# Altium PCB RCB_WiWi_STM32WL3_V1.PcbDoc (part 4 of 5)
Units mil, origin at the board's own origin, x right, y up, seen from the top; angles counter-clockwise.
Board outline 1250.1 x 2647.64 mil, 10 copper layers (L01-TOP, L02-GND, L03-SIG, L04-GND, L05-PWR, L06-PWR, L07-GND, L08-SIG, L09-GND, L10-BOT), stack 62.1 mil thick; 342 components, 203 nets, 969 pads, 708 vias.
Unrouted connection lines stored in the file: 108.
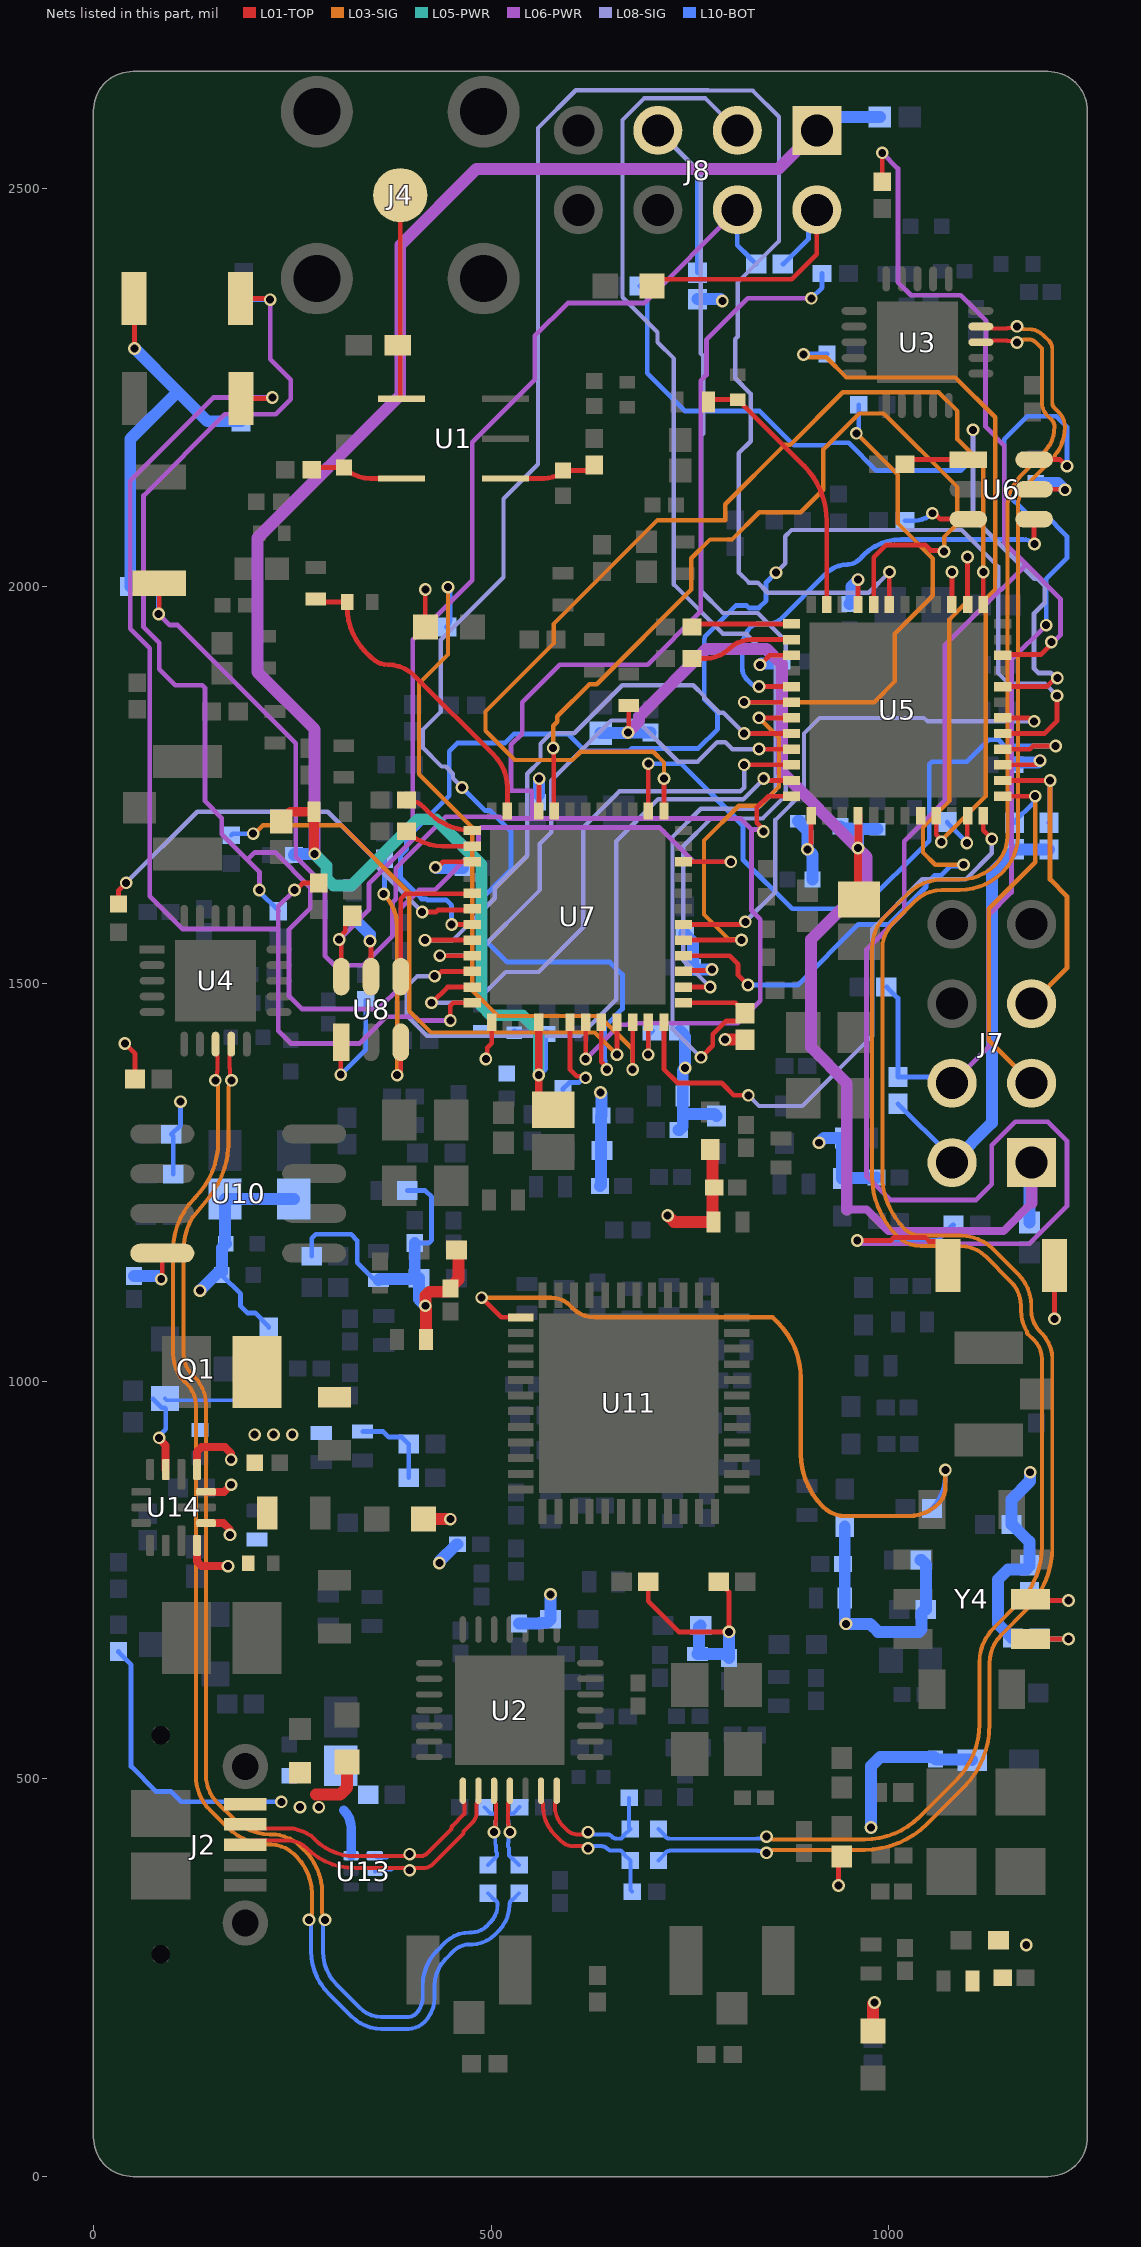
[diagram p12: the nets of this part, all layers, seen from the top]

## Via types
v1: diameter 16, hole 10, L01-TOP to L10-BOT, tented both sides, 699 vias
v2: diameter 16, hole 10, L01-TOP to L10-BOT, 9 vias

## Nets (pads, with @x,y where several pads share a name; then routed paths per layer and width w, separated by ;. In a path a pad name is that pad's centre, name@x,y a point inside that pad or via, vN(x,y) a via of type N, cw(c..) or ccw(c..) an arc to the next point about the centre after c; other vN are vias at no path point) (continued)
P3V3: C22.1 C23.1 C40.1 C41.1 C45.2 C54.2 C55.1 C71.1 C72.1 C76.1 C86.1 C90.1 C91.1 C96.1 C100.1 C101.1 C104.1 C106.1 C112.1 C113.1 C131.1 C132.1 C135.1 C137.1 C138.1 C139.1 C140.1 C141.2 C147.1 C148.1 C151.1 C153.1 C154.1 C155.1 C156.1 C157.2 D1.2 D2.2 D8.2 FB2.2 J7.2 J8.2 L2.1 L3.1 L6.1 L8.1 L10.2 L11.1 L13.1 L14.1 L16.1 L26.1 L29.1 R3.2 R18.1 R19.1 R20.2 R21.2 R22.1 R23.1 R28.2 R29.2 R31.2 R32.2 R49.2 R50.2 R52.1 R58.1 R69.1 R74.1 R78.1 R89.2 R90.2 R91.1 R95.2 R96.2 R101.1 R110.2 R111.2 R112.1 SW1.2 SW3.2 U5.3 U5.21 U5.27 U5.37 U6.5 U7.3 U7.21 U7.27 U7.37 U8.5 U10.8 | length 5166.3
  L01-TOP w6: v1(39.37,1425.2) 52.26,1412.31 R69.1@52.26,1380.51 ; SW3.2@51.18,2362.2 51.71,2361.68 v1(51.71,2299.21) ; v1(85.24,1128.61) 86.61,1129.98 U10.8@86.61,1161.42 ; v1(347.83,1553.87) 349.07,1552.63 U8.5@349.07,1509.25 ; v1(417.32,1996.06) 417.32,1949.18 D8.2@417.44,1949.06 ; v1(430.06,1646.7) 432.77,1646.7 439.61,1653.55 U7.27@476.38,1653.55 ; v1(493.43,1405.51) 495.34,1407.43 495.34,1419.88 500.97,1425.51 U7.37@500.98,1451.76 ; U7.21@560.04,1717.51 560.34,1717.81 560.34,1757.92 v1(560.64,1758.22) ; R32.2@697.83,748.03 697.83,723.43 736.22,685.04 v1(799.21,685.04) 799.21,735.24 796.21,738.24 796.21,739.22 787.4,748.03 R22.1@786.42,748.03 ; D2.2@702.76,2377.95 711.01,2386.2 878.33,2386.2 909.84,2417.72 J8.2@909.84,2473.62 ; U7.3@742.13,1515.72 743.39,1516.99 776.77,1516.99 v1(778.04,1518.26) ; v1(838.36,1901.35) 850.4,1913.4 U5.27@877.95,1913.4 ; v1(898.16,1669.29) 898.16,1672 902.56,1676.4 U5.37@902.56,1711.61 ; v1(937.01,366.14) 937.01,398.62 R3.2@940.94,402.56 ; U5.21@961.61,1977.35 961.66,1977.4 v1(961.71,2008.46) v1(961.71,2008.46) ; U5.3@1143.7,1775.57 1185.35,1775.57 v1(1190.6,1780.82) ; U6.5@1183.09,2122.05 1221.4,2122.05 v1(1221.99,2121.47) ; v1(1208.66,1078.74) SW1.2@1208.66,1145.67
  L01-TOP w15: C147.1@418.33,1052.98 418.33,1093.96 417.32,1094.97 v1(417.32,1095.24) 417.51,1095.43 417.51,1107.97 422.36,1112.82 446.24,1112.82 448.82,1115.4 448.82,1118.11 458.9,1128.19 458.9,1163.15 L29.1@456.69,1165.35 ; v1(722.13,1208.66) 722.41,1208.66 730.28,1200.79 C131.1@780.02,1200.79 778.66,1202.15 778.66,1288.87 L26.1@775.84,1291.69 ; v1(794.3,1430.11) 794.47,1429.93 819.41,1429.93 R111.2@819.58,1429.76 ; D1.2@980.31,183.07 980.31,216.88 v1(982.3,218.87)
  L10-BOT w6: R19.1@100.32,1260.63 100.32,1308.65 R18.1@98,1310.97 109.54,1322.52 v1(109.54,1351.94) ; R21.2@274.61,1157.48 274.61,1180.12 279.53,1185.04 323.97,1185.04 331.85,1177.17 331.85,1149.45 353.84,1127.46 C71.1@358.27,1127.46 ; C41.1@338.58,937.01 364.4,937.01 371.33,930.07 387.84,930.07 R50.2@396.65,921.26 396.58,921.18 R49.2@396.58,878.76 ; R20.2@394.69,1240.16 417.32,1240.16 425.2,1232.28 425.2,1177.54 421.68,1174.03 C96.1@404.08,1174.03 ; R112.1@867.13,2405.51 868.11,2405.51 899.16,2436.57 899.16,2462.94 J8.2@909.84,2473.62 ; R91.1@1011.81,1349.41 1075.61,1285.61 cw(c1065.19,1275.2) J7.2@1079.92,1275.2
  L10-BOT w15: R78.1@46.26,2000 46.26,2185.41 105.89,2245.03 ; C55.1@51.18,1132.5 81.09,1132.5 84.97,1128.61 v1(85.24,1128.61) ; v1(51.71,2299.21) 105.89,2245.03 ; R101.1@185.57,2207.68 143.24,2207.68 105.89,2245.03 ; C151.1@327.45,1582.68 347.64,1562.49 347.64,1554.06 v1(347.83,1553.87) ; C71.1@358.27,1127.46 359.5,1128.69 408.22,1128.69 L11.1@409.45,1129.92 ; C96.1@404.08,1174.03 404.08,1134.23 408.4,1129.92 L11.1@409.45,1129.92 ; v1(417.32,1095.24) 417.32,1095.51 409.45,1103.38 L11.1@409.45,1129.92 ; v1(430.06,1646.7) 430.33,1646.7 431.37,1645.67 C155.1@464.57,1645.67 ; v1(435.04,771.65) 435.23,771.84 435.23,773.81 456.69,795.28 R52.1@457.68,795.28 ; C76.1@535.43,695.49 560.23,695.49 561.21,696.48 570.49,696.48 L3.1@574.8,700.79 v1(574.8,732.28) ; C154.1@560.45,1737.61 560.45,1758.03 v1(560.64,1758.22) ; C86.1@637.16,1246 638.16,1246.99 638.16,1333.65 C72.1@639.15,1334.65 639.15,1362.18 v1(637.81,1363.52) ; C101.1@736.02,1316.46 737.37,1316.46 741.17,1320.25 741.17,1336.39 ; R74.1@736.9,1440.93 737.89,1440.93 742.2,1436.62 742.2,1435.64 744.25,1433.59 v1(744.25,1394.25) 741.17,1391.18 C100.1@741.17,1359.19 741.17,1336.39 ; R31.2@743.63,1563.96 743.63,1562.98 753.83,1552.78 C153.1@753.83,1521 756.56,1518.26 v1(778.04,1518.26) ; C104.1@759.84,656.99 C104.1@760.45,656.99 ; R110.2@759.84,2361.22 788.73,2361.22 v1(790.88,2359.07) ; L14.1@763.78,692.91 761.81,690.94 761.81,658.35 C104.1@760.45,656.99 ; L13.1@783.72,1333.74 781.07,1336.39 741.17,1336.39 ; C106.1@799.21,652.19 C106.1@799.21,653.54 ; v1(799.21,685.04) C106.1@799.21,653.54 ; v1(838.36,1901.35) 838.63,1901.35 840.05,1902.78 863.41,1902.78 C139.1@866.14,1905.51 ; C140.1@885.83,1704.72 887.8,1704.72 888.17,1704.35 888.17,1702.38 897.97,1692.58 897.97,1669.48 v1(898.16,1669.29) 898.16,1669.02 904.33,1662.85 C141.2@904.33,1631.21 ; v1(912.58,1300.22) 918.56,1306.2 C90.1@941.3,1306.2 941.49,1306 941.49,1255.61 L8.1@941.69,1255.42 942.18,1255.91 984.48,1255.91 C91.1@984.98,1256.41 ; C112.1@944.93,727.66 944.93,696.74 v1(946.57,695.09) 946.76,694.9 977.04,694.9 986.88,685.05 1038.18,685.05 1041.67,688.54 1041.67,708.88 1045.98,713.19 R29.2@1046.97,713.19 1046.97,769.96 1041.34,775.59 R28.2@1040.35,775.59 ; C112.1@944.93,727.66 L16.1@944.88,817.42 ; C138.1@950.77,1977.86 953.5,1980.6 953.5,1999.98 961.71,2008.19 v1(961.71,2008.46) ; v1(978.05,439.06) 977.96,439.15 977.96,516.08 989.56,527.67 1057.25,527.67 1059.06,525.87 C54.2@1059.06,524.93 1059.71,524.27 1104.66,524.27 FB2.2@1105.31,523.62 ; J7.2@1079.92,1275.2 1129.92,1325.2 1129.92,1639.96 1158.27,1668.31 R90.2@1158.27,1669.3 1158.4,1669.17 1201.57,1669.17 R89.2@1201.7,1669.04 ; R95.2@1156.5,677.17 1155.51,677.17 1137.8,694.88 1137.8,751.06 1150.15,763.41 1172.85,763.41 1177.17,767.72 R96.2@1177.17,768.7 1177.17,798.57 1155.71,820.02 R23.1@1154.72,820.02 1154.72,851.58 1177.92,874.77 1177.92,885.64 v1(1178.11,885.83) ; C137.1@1159.45,1775.57 1162.18,1778.3 1187.81,1778.3 1190.33,1780.82 v1(1190.6,1780.82) ; C135.1@1185.04,2129.92 1213.26,2129.92 1221.71,2121.47 v1(1221.99,2121.47) ; C104.1@760.45,656.99 794.41,656.99 795.27,656.12 796.63,656.12 C106.1@799.21,653.54
  other v1: 1173.23,291.34 202.76,933.07 226.38,933.07 250,933.07
P3V3_PGOOD: Q1.1 R53.1 U14.13 | length 277.9
  L01-TOP w10: v1(82.68,929.13) 82.68,927.51 90.87,919.32 U14.13@90.87,889.27
  L10-BOT w5: Q1.1@89.8,978.35 91.77,976.38 192.91,976.38 220.47,1003.94 R53.1@220.47,1034.45
  L10-BOT w6: Q1.1@74.8,978.35 86.17,966.98 89.49,966.98 90.87,965.6 90.87,940.03 82.68,931.84 v1(82.68,929.13)
RX_BOOTSEL: R59.2 R75.1 SW1.1 U5.10 | length 2692.8
  L01-TOP w6: v1(960.63,1177.17) 1002.71,1177.17 1006.64,1181.1 1046.01,1181.1 1050.98,1176.13 1062.06,1176.13 1074.8,1163.39 SW1.1@1074.8,1145.67 ; v1(992.07,2545.24) 992.13,2545.19 R59.2@992.13,2508.86 ; U5.10@1143.7,1913.4 1144.72,1914.42 1191.81,1914.42 1204.72,1927.33 v1(1204.72,1930.04)
  L06-PWR w6: v1(960.63,1177.17) 963.34,1177.17 967.27,1173.23 1177.17,1173.23 1224.41,1220.47 1224.41,1302.84 1200.48,1326.77 1159.36,1326.77 1129.92,1297.33 1129.92,1248.03 1110.24,1228.35 1001.98,1228.35 972.44,1257.89 972.44,1543.31 1019.68,1590.55 1019.68,1679.39 1070.87,1730.57 1070.87,1926.18 1140.74,1996.06 1141.73,1996.06 1171.76,2026.09 1171.76,2029.03 ; v1(992.07,2545.24) 1011.81,2525.5 1011.81,2382.57 1028.24,2366.14 1090.55,2366.14 1122.66,2334.03 1122.66,2312.01 1122.05,2311.39 1122.05,2200.79 1145.67,2177.17 1145.67,2055.12 1171.76,2029.03 ; v1(1204.72,1930.04) 1207.43,1930.04 1216.23,1938.84 1216.23,1984.56 1171.76,2029.03
  L10-BOT w6: v1(960.63,1177.17) 1061.02,1177.17 1080.71,1196.85 R75.1@1081.69,1196.85
RX_CLK: U5.29 U6.4 | length 558.1
  L01-TOP w6: v1(837.2,1874.11) 837.29,1874.01 U5.29@877.95,1874.02 ; U6.4@1183.09,2084.65 1183.09,2053.68 v1(1183.55,2053.22)
  L10-BOT w6: 822.12,1882.61 825.97,1878.76 ccw(c837.2,1889.99) 829.64,1876.02 ccw(c837.2,1889.99) v1(837.2,1874.11) ; 822.1,1882.62 cw(c837.1,1897.59) 815.91,1897.59 815.91,1922.6 cw(c852.99,1922.6) 826.77,1948.82 cw(c836.32,1939.27) 836.32,1952.78 848.14,1952.78 ccw(c848.14,1977.29) 865.47,1959.95 921.94,2016.42 cw(c948.82,1989.54) 948.82,2027.56 ccw(c948.82,2046.57) 962.26,2033.13 968.5,2039.37 cw(c1016.03,1991.85) 1016.03,2059.06 1169.46,2059.06 cw(c1169.46,2039.14) v1(1183.55,2053.22)
RX_CLK_SEL: J7.4 R91.2 R92.1 U6.6 | length 1295.9
  L01-TOP w6: U6.6@1183.09,2159.45 1215.81,2159.45 1224.08,2151.18 v1(1224.43,2151.18)
  L06-PWR w6: J7.4@1079.92,1375.2 1125.98,1421.26 1125.98,1586.61 1154.53,1615.16 1154.53,1907.48 v1(1198.3,1951.25)
  L10-BOT w6: R92.1@997.05,1496.06 998.03,1496.06 1011.81,1482.28 R91.2@1011.81,1382.87 1061.39,1382.87 cw(c1061.39,1356.66) J7.4@1079.92,1375.2 ; v1(1198.3,1951.25) 1198.3,2009.32 1224.41,2035.43 1224.41,2062.99 1196.85,2090.55 1174.8,2090.55 1145.67,2119.69 1145.67,2185.04 1174.68,2214.05 1211.15,2214.05 1224.43,2200.76 v1(1224.43,2151.18)
RX_DETECT: R73.1 U5.47 | length 71.5
  L01-TOP w6: v1(1098.43,1677.17) 1098.92,1677.66 1098.92,1711.11 U5.47@1099.41,1711.61
  L10-BOT w6: R73.1@1073.82,1703.65 1073.82,1702.67 1098.43,1678.06 v1(1098.43,1677.17)
RX_DPLL_48MHz: R87.2 U6.3 | length 85.3
  L01-TOP w6: v1(1055.12,2092.02) 1057.82,2092.02 1065.2,2084.65 U6.3@1100.37,2084.65
  L10-BOT w6: R87.2@1020.67,2082.68 1032.56,2082.68 ccw(c1032.56,2114.58) v1(1055.12,2092.02)
RX_FTDI_USB_N: C116.2 R13.1 U2.6 | length 210
  L01-TOP w5: U2.6@562.99,485.24 562.99,473.32 ccw(c566.99,473.32) 564.16,470.49 cw(c561.34,467.66) 565.33,467.66 565.33,465.55 ccw(c615.08,465.55) 579.91,430.38 588.23,422.05 ccw(c604.24,438.06) 604.24,415.42 619.4,415.42 cw(c619.4,412.77) v1(622.05,412.77)
  L10-BOT w5: v1(622.05,412.77) cw(c624.7,412.77) 624.7,415.42 638.99,415.42 cw(c638.99,405.86) 645.75,412.62 ccw(c652.5,419.38) 652.5,409.82 661.87,409.82 cw(c661.87,404.82) 665.4,408.36 666.87,406.89 ccw(c669.11,406.89) 667.52,405.31 R13.1@675.2,397.64 675.2,360.63 C116.2@677.56,358.27
RX_FTDI_USB_P: C53.2 R14.1 U2.7 | length 185.8
  L01-TOP w5: U2.7@582.68,485.24 582.68,473.32 cw(c578.68,473.32) 581.51,470.49 ccw(c584.33,467.66) 580.33,467.66 580.33,465.61 ccw(c615.22,465.61) 590.55,440.95 596.64,434.86 ccw(c607.35,445.56) 607.35,430.42 619.4,430.42 ccw(c619.4,433.07) v1(622.05,433.07)
  L10-BOT w5: v1(622.05,433.07) ccw(c624.7,433.07) 624.7,430.42 645.2,430.42 cw(c645.2,420.86) 651.96,427.62 ccw(c658.72,434.38) 658.72,424.82 661.87,424.82 ccw(c661.87,429.82) 665.4,426.28 666.87,427.75 cw(c669.11,427.75) 667.53,429.34 R14.1@675.2,437.01 673.62,438.58 C53.2@673.62,476.38
RX_LCL_48MHz: R83.2 U6.1 | length 82.2
  L01-TOP w6: R83.2@1020.67,2153.54 1026.57,2159.45 U6.1@1100.37,2159.45
RX_LED0: R72.1 U5.8 | length 1071.9
  L01-TOP w6: U5.8@1143.7,1874.02 1198.94,1874.02 1209.67,1884.74 v1(1212.26,1884.74)
  L08-SIG w6: v1(1106.3,2196.85) 1106.3,2086.61 1183.37,2009.54 1187.44,2009.54 1196.4,2000.58 1196.4,1979.45 1183,1966.04 1183,1896.64 1188.55,1891.08 1203.74,1891.08 1210.08,1884.74 v1(1212.26,1884.74)
  L10-BOT w6: R72.1@687.01,2377.95 687.69,2377.95 696.5,2369.14 696.5,2268.06 744.09,2220.47 838.05,2220.47 880.91,2177.61 923.66,2177.61 926.7,2180.65 949.81,2180.65 984.8,2145.67 1090.55,2145.67 1106.3,2161.42 v1(1106.3,2196.85)
RX_LED2: U5.15 | length 40.8
  L01-TOP w6: U5.15@1079.72,1977.35 1079.72,2018.02 v1(1079.82,2018.11)
RX_RF: C30.1 R9.2 U1.3 | length 117.2
  L01-TOP w6: U1.3@518.26,2135.79 566.69,2135.79 ccw(c566.69,2169.53) C30.1@590.55,2145.67 623.03,2145.67 R9.2@629.92,2152.56
RX_RF_RX: C20.1 L25.1 U5.23 | length 337.2
  L01-TOP w6: L25.1@773.66,2231.89 cw(c781.17,2224.38) 781.17,2235 C20.1@810.41,2235 892.95,2152.45 cw(c822.24,2081.74) 922.24,2081.74 U5.23@922.24,1977.35
RX_RF_TX: R5.1 U5.26 | length 131.3
  L01-TOP w6: R5.1@752.95,1909.45 770.7,1909.45 ccw(c770.7,1949.77) 799.21,1921.26 cw(c827.76,1892.71) 827.76,1933.09 U5.26@877.95,1933.09
RX_RF_TX_HP: R6.1 U5.25 | length 126.1
  L01-TOP w6: R6.1@752.95,1948.82 cw(c762.51,1939.26) 762.51,1952.78 U5.25@877.95,1952.78
RX_RST_N: R57.2 R78.2 SW2.1 U5.36 U7.43 | length 2870.6
  L01-TOP w6: v1(81.93,1965.25) 82.68,1966 SW2.1@82.68,2003.94 ; v1(619.09,1405.51) U7.43@619.09,1451.76 ; v1(842.58,1691.68) 842.58,1694.38 834.2,1702.76 834.2,1721.96 848.43,1736.19 U5.36@877.95,1736.19
  L06-PWR w6: v1(81.93,1965.25) 95.81,1951.37 105.7,1951.37 254.48,1802.59 254.48,1659.89 291.05,1623.32 291.05,1535.72 303.15,1523.62 339.22,1523.62 376.17,1560.57 376.17,1602.52 380.28,1606.63 380.28,1645.25 411.87,1676.84 411.87,1678.72 443.34,1710.19 510.85,1710.19 512.8,1708.23 551.18,1708.23 ; v1(619.09,1405.51) 662.15,1448.57 672.24,1448.57 674.11,1450.43 810.08,1450.43 838.58,1478.94 838.58,1581.12 827.79,1591.91 827.79,1694.09 ; v1(842.58,1691.68) 840.66,1693.59 836.18,1693.59 835.68,1694.09 827.79,1694.09 ; v1(902.9,2362.33) 822.96,2362.33 770.95,2310.32 770.95,2265.93 763.78,2258.75 763.78,1968.5 696.85,1901.57 586.61,1901.57 539.37,1854.33 539.37,1814.96 525.11,1800.7 525.11,1743.06 551.18,1743.06 551.18,1708.23 ; 551.18,1708.23 813.65,1708.23 827.79,1694.09
  L10-BOT w6: R78.2@79.72,2000 81.93,1997.8 v1(81.93,1965.25) ; v1(902.9,2362.33) 916.34,2375.77 R57.2@916.34,2393.7
RX_RX_SEQUENCE: R76.1 U7.42 | length 118.7
  L01-TOP w6: U7.42@599.41,1451.76 599.4,1392.25 607.84,1383.8 617.18,1383.8 v1(619.09,1381.89)
  L10-BOT w6: R76.1@590.55,1367.13 590.55,1368.11 598.38,1375.94 610.44,1375.94 616.39,1381.89 v1(619.09,1381.89)
RX_SPI1_MISO: U5.35 U7.34 | length 873.2
  L01-TOP w6: v1(429.13,1509.81) 431.84,1509.81 437.75,1515.72 U7.34@476.38,1515.72 ; v1(842.97,1758.32) 845.67,1758.32 848.11,1755.88 U5.35@877.95,1755.88
  L08-SIG w5.5: v1(429.13,1509.81) 407.45,1509.81 393.7,1496.06 393.7,1460.63 419.46,1434.87 612.03,1434.87 657.48,1480.32 657.48,1679.46 710.16,1732.15 817.48,1732.15 842.97,1757.64 v1(842.97,1758.32)
RX_SPI1_MOSI: U5.34 U7.35 | length 726.7
  L01-TOP w6: v1(425.04,1476.34) 425.66,1476.34 445.34,1496.02 U7.35@476.38,1496.03 ; v1(818.43,1775.56) U5.34@877.95,1775.57
  L08-SIG w5.5: v1(425.04,1476.34) 479.7,1476.34 518.41,1515.05 559.98,1515.05 616.08,1571.15 616.08,1696.85 661.46,1742.24 813.71,1742.24 818.43,1746.96 v1(818.43,1775.56)
RX_SPI1_NSS: U5.33 U7.33 | length 713.2
  L01-TOP w6: v1(435.62,1535.5) 435.72,1535.4 U7.33@476.38,1535.41 ; v1(837.2,1795.35) 837.29,1795.25 U5.33@877.95,1795.26
  L08-SIG w5.5: v1(435.62,1535.5) 478.78,1535.5 561.51,1618.22 561.51,1676.3 575.69,1690.48 575.69,1755.73 651.36,1831.4 683.56,1831.4 735.43,1779.53 759.84,1779.53 784.35,1804.03 794.79,1804.03 803.48,1795.35 v1(837.2,1795.35)
RX_SPI1_SCK: U5.32 U7.32 | length 759.4
  L01-TOP w6: v1(416.86,1555.09) U7.32@476.38,1555.1 ; v1(818.43,1814.94) U5.32@877.95,1814.95
  L08-SIG w5.5: v1(416.86,1555.09) 452.06,1555.09 504.63,1607.67 504.63,1620.41 545.59,1661.36 545.59,1764.45 562.29,1781.16 562.29,1802.1 575.46,1815.26 604.66,1815.26 664.92,1875.53 754.27,1875.53 768.41,1861.38 768.41,1859.91 787.23,1841.1 792.28,1841.1 v1(818.43,1814.94)
RX_SPI3_MISO: U5.5 U7.31 | length 1609.4
  L01-TOP w6: v1(450.47,1574.79) U7.31@476.38,1574.79 ; U5.5@1143.7,1814.95 1196.14,1814.95 1212.01,1830.82 v1(1212.01,1862.45)
  L08-SIG w5.5: v1(858.38,2017.26) 870.08,2028.96 870.08,2062.99 877.95,2070.87 1091.99,2070.87 1137.79,2025.06 1137.79,1891.02 1151.08,1877.74 1196.72,1877.74 v1(1212.01,1862.45)
  L10-BOT w6: v1(450.47,1574.79) 450.47,1599.01 443.82,1605.66 419.99,1605.66 418.69,1606.96 412.74,1606.96 386.27,1633.43 386.27,1661.87 393.7,1669.29 393.7,1683.05 447.34,1736.7 447.34,1792.52 457.97,1803.15 517.7,1803.15 529.06,1814.51 596.71,1814.51 618.13,1793.09 673.94,1793.09 677.03,1796.18 760.75,1796.18 784.92,1820.35 784.92,1841.06 768.16,1857.81 768.16,1933.52 768.73,1934.08 768.73,1936.56 808.05,1975.89 821.37,1975.89 824.37,1972.89 837.05,1972.89 846.01,1981.85 846.01,2004.89 v1(858.38,2017.26)
RX_SPI3_MOSI: U5.31 U7.5 | length 486.5
  L01-TOP w6: U7.5@742.13,1555.1 v1@814.95,1555.11 ; v1(837.2,1834.73) 837.29,1834.63 U5.31@877.95,1834.64
  L03-SIG w5.5: v1(814.96,1555.12) 813.64,1556.44 798.71,1556.44 767.83,1587.32 767.83,1680.41 811.57,1724.14 838.14,1724.14 862.2,1748.2 862.2,1809.72 v1(837.2,1834.73)
RX_SPI3_NSS: U5.6 U7.6 | length 687.1
  L01-TOP w6: U7.6@742.13,1574.79 813.84,1574.79 817.2,1578.15 v1(819.91,1578.15) ; U5.6@1143.7,1834.64 1176.05,1834.64 1180.43,1830.25 v1(1183.14,1830.25)
  L08-SIG w5.5: v1(819.91,1578.15) 857.72,1615.97 857.72,1706.34 893.7,1742.32 893.7,1814.95 913.3,1834.54 1044.65,1834.54 1048.94,1830.25 v1(1183.14,1830.25)
RX_SPI3_SCK: U5.13 U7.13 | length 1387.1
  L01-TOP w6: U7.13@717.52,1717.51 717.52,1758.17 v1(717.62,1758.26) ; U5.13@1119.09,1977.35 1119.09,2018.02 v1(1119.19,2018.11)
  L03-SIG w5.5: v1(717.62,1758.26) 717.62,1778.52 704.06,1792.08 612.86,1792.08 602.5,1781.72 529.92,1781.72 493.11,1818.52 493.11,1842.51 578.74,1928.14 578.74,1952.76 709.34,2083.36 794.58,2083.36 794.58,2103.26 869.28,2177.96 876.41,2177.96 942.54,2244.09 1062.99,2244.09 1086.61,2220.47 1086.61,2185.04 1119.19,2152.47 v1(1119.19,2018.11)
RX_SWCLK: J7.5 R89.1 U5.2 | length 421.4
  L01-TOP w6: U5.2@1143.7,1755.88 v1(1203.22,1755.88)
  L03-SIG w6: J7.5@1179.92,1475.2 1224.41,1519.68 1224.41,1610.24 1203.22,1631.43 v1(1203.22,1755.88)
  L10-BOT w6: R89.1@1201.7,1702.51 1203.22,1704.03 v1(1203.22,1755.88)
RX_SWDIO: J7.3 R90.1 U5.1 | length 492.4
  L01-TOP w6: U5.1@1143.7,1736.19 1184.36,1736.19 v1(1184.46,1736.09)
  L03-SIG w6: J7.3@1179.92,1375.2 1125.98,1429.13 1125.98,1594.49 1184.46,1652.96 v1(1184.46,1736.09)
  L10-BOT w6: R90.1@1158.27,1702.76 1158.27,1703.75 1182.55,1728.02 1182.55,1734.18 v1(1184.46,1736.09)
RX_TX_SEQUENCE: U5.19 U7.44 | length 2733
  L01-TOP w6: U7.44@638.78,1451.76 638.78,1401.84 645.67,1394.95 v1(645.67,1392.24) ; U5.19@1000.98,1977.35 1000.98,2018.02 v1(1001.08,2018.11)
  L08-SIG w5.5: v1(463.54,1747.01) 463.54,1747.44 452.27,1758.72 452.27,1764.27 443.01,1773.53 437.86,1773.53 414.37,1797.01 414.37,1819.88 437.01,1842.52 437.01,1932.77 515.75,2011.51 515.75,2110.24 559.06,2153.54 559.06,2576.51 606.52,2623.97 773.35,2623.97 773.62,2623.71 829.05,2623.71 862.2,2590.55 862.2,2434.31 810.12,2382.22 810.12,2314.06 807.09,2311.02 807.09,2261.81 826.77,2242.13 826.77,2182.7 811.72,2167.65 811.72,2017.39 824.35,2004.76 835.42,2004.76 848.06,1992.13 975.09,1992.13 v1(1001.08,2018.11)
  L10-BOT w6: v1(463.54,1747.01) 492.36,1718.19 498.35,1718.19 525.25,1691.29 525.25,1644.06 487.2,1606.01 487.2,1560.76 520.41,1527.56 649.61,1527.56 665.35,1511.81 665.35,1468.5 643.06,1446.21 643.06,1404.66 643.76,1403.97 643.76,1394.15 v1(645.67,1392.24)
RX_USART1_RX: R11.2 U5.45 | length 901.5
  L01-TOP w6: U5.45@1060.04,1711.61 1060.04,1687.6 1066.38,1681.26 v1(1066.38,1678.56)
  L03-SIG w5.5: v1(893.09,2291.75) 895.93,2291.75 899.48,2288.21 921.59,2288.21 947,2262.8 1084.03,2262.8 1134.24,2212.59 1134.24,2010.39 1133.86,2010.02 1133.86,1996.06 1122.05,1984.25 1122.05,1735.95 1066.38,1680.28 v1(1066.38,1678.56)
  L10-BOT w6: v1(893.09,2291.75) 893.53,2292.19 R11.2@922.66,2292.19
RX_USART1_TX: R12.2 U5.30 | length 668.7
  L01-TOP w6: v1(818.43,1854.32) U5.30@877.95,1854.33
  L03-SIG w5.5: v1(818.43,1854.32) 981.9,1854.32 1007.87,1880.3 1007.87,1940.32 1055.74,1988.18 1055.74,2035.12 1011.81,2079.04 1011.81,2140.3 v1(959.56,2192.55)
  L10-BOT w6: v1(959.56,2192.55) 962.6,2195.59 R12.2@962.6,2228.35
RX_VFBSD: C13.1 C14.2 C130.1 C142.1 C143.1 J7.1 L21.2 L27.1 U5.40 | length 1686.5
  L01-TOP w6: v1(672.34,1816.35) 673.23,1817.24 L21.2@673.23,1850.2
  L01-TOP w10: v1(961.52,1670.85) 961.52,1607.58 L27.1@962.83,1606.27 ; U5.40@961.61,1711.61 962.1,1711.12 v1@962.1,1671.43
  L06-PWR w10: 947.47,1216.54 972.44,1216.54 1000,1188.98 1144.49,1188.98 1179.92,1224.41
  L06-PWR w15: v1(672.34,1816.35) 672.34,1816.62 686.22,1830.5 686.22,1836.67 770.81,1921.26 846.46,1921.26 866.14,1901.57 866.14,1766.22 v1(961.52,1670.85) 961.52,1670.58 972.44,1659.65 972.44,1625.98 902.56,1556.1 902.56,1420.14 947.47,1375.22 947.47,1216.54 ; 1179.92,1224.41 J7.1@1179.92,1275.2
  L10-BOT w15: C14.2@637.8,1815.35 671.07,1815.35 672.07,1816.35 v1(672.34,1816.35) C13.1@700.79,1816.32 ; C143.1@939.61,1698.29 942.35,1695.56 952.94,1695.56 953.68,1694.82 961.52,1694.82 ; v1(961.52,1670.85) 961.52,1694.82 ; C142.1@986.02,1694.82 961.52,1694.82 ; C130.1@1177.17,1199.94 1177.17,1272.44 J7.1@1179.92,1275.2
SiT5501_PLL_SCL: R96.1 Y4.3 | length 102.7
  L01-TOP w6: Y4.3@1178.54,725.99 1180.12,724.41 v1(1226.33,724.41)
  L10-BOT w6: R96.1@1177.17,735.24 1177.17,734.25 1185.98,725.44 1186.96,725.44 1187.99,724.41 v1(1226.33,724.41)
SiT5501_PLL_SDA: R95.1 Y4.2 | length 84.6
  L01-TOP w6: Y4.2@1178.54,675.99 v1(1226.33,675.99)
  L10-BOT w6: R95.1@1189.96,677.17 1191.14,675.99 v1(1226.33,675.99)
TCXO_10M: R26.1 U11.1 | length 938.9
  L01-TOP w6: v1(488.19,1105.32) 512.8,1080.71 U11.1@537.23,1080.71
  L03-SIG w5.5: v1(488.19,1105.32) 575.66,1105.32 cw(c575.66,1071.84) 599.33,1095.51 602.75,1092.09 ccw(c630.48,1119.81) 630.48,1080.6 854.25,1080.6 860.47,1074.38 cw(c789.76,1003.67) 889.76,1003.67 889.76,909.05 ccw(c983.86,909.05) 917.32,842.52 ccw(c945.84,871.03) 945.84,830.71 1024.97,830.71 ccw(c1024.97,884.48) 1062.99,846.46 ccw(c1042.56,866.89) 1071.46,866.89 v1(1071.46,888.72)
  L10-BOT w6: R26.1@1054.72,840.16 ccw(c1014.33,880.55) 1071.46,880.55 v1(1071.46,888.72)
TX_BOOTSEL: R68.2 R100.1 SW3.1 U7.10 | length 2107.5
  L01-TOP w6: SW3.1@185.04,2362.2 220.63,2362.2 v1(222.27,2360.57) ; U7.10@742.13,1653.55 v1(801.64,1653.55)
  L06-PWR w6: v1(208.66,1618.11) 208.66,1641.12 193.68,1656.1 ; v1(222.27,2360.57) 222.27,2285.61 248.03,2259.84 248.03,2235.3 229.27,2216.54 165.35,2216.54 62.99,2114.17 62.99,1948.82 82.68,1929.13 82.68,1895.69 102.77,1875.59 136.79,1875.59 140.31,1872.07 140.31,1729.77 161.42,1708.66 161.42,1688.36 193.68,1656.1 ; v1(801.64,1653.55) 754.75,1653.55 711.45,1696.85 487.77,1696.85 484.25,1693.34 484.25,1673.24 429.12,1618.11 409.45,1618.11 386.47,1595.14 386.47,1496.71 358.27,1468.5 261.83,1468.5 246.06,1484.27 246.06,1568.59 272.64,1595.16 272.64,1621.05 228.33,1665.35 202.93,1665.35 193.68,1656.1
  L10-BOT w6: R100.1@188.98,2360.57 v1(222.27,2360.57) ; v1(208.66,1618.11) 208.66,1616.14 232.28,1592.52 R68.2@232.28,1591.54
TX_CLK: U7.29 U8.4 | length 190.6
  L01-TOP w6: U8.4@386.47,1509.25 386.47,1606.95 392.85,1613.32 475.53,1613.32 U7.29@476.38,1614.17
TX_CLK_SEL: J8.4 R112.2 R113.1 U8.6 | length 1344.4
  L01-TOP w6: U8.6@311.67,1509.25 311.67,1553.11 v1(308.97,1555.81) 308.97,1558.52 316.63,1566.18 316.63,1576.82 R113.1@325.45,1585.63
  L06-PWR w6: v1(308.97,1555.81) 346.46,1593.3 346.46,1625.98 401.57,1681.1 401.57,1933.07 476.38,2007.87 476.38,2181.1 555.12,2259.84 555.12,2314.96 596.46,2356.3 692.52,2356.3 J8.4@809.84,2473.62
  L10-BOT w6: J8.4@809.84,2473.62 809.84,2429.33 823.87,2415.31 823.87,2414.32 832.68,2405.51 R112.2@833.66,2405.51
TX_DETECT: R74.2 U7.47 | length 73.1
  L01-TOP w6: v1(697.74,1411) 697.83,1411.1 U7.47@697.83,1451.76
  L10-BOT w6: v1(697.74,1411) 697.74,1435.23 R74.2@703.44,1440.93
TX_DPLL_48MHz: R108.2 U8.3 | length 320.5
  L01-TOP w6: v1(382.03,1385.21) 386.47,1389.65 U8.3@386.47,1426.54
  L03-SIG w5.5: v1(364.98,1612.97) cw(c323.83,1571.81) 382.03,1571.81 v1(382.03,1385.21)
  L10-BOT w6: v1(364.98,1612.97) 366.14,1614.12 R108.2@366.14,1657.48
TX_FTDI_USB_N: C124.2 R64.1 U2.3 | length 142.8
  L01-TOP w5: v1(503.63,433.07) 505.73,435.18 505.73,447.1 506.28,447.65 506.28,467.66 ccw(c502.28,467.66) 505.11,470.49 cw(c507.94,473.32) 503.94,473.32 U2.3@503.94,485.24
  L10-BOT w5: C124.2@491.63,464.46 499.37,456.72 503.32,456.72 506.25,453.79 506.25,447.62 505.73,447.1 505.73,435.18 v1(503.63,433.07) 505.32,431.38 505.32,417.57 506.28,416.61 506.28,408.58 507.73,407.13 507.73,402.99 504.8,400.06 504.39,400.06 R64.1@496.06,391.73
TX_FTDI_USB_P: C123.2 R65.1 U2.4 | length 143.7
  L01-TOP w5: U2.4@523.62,485.24 523.62,473.32 cw(c519.62,473.32) 522.45,470.49 ccw(c525.28,467.66) 521.28,467.66 521.28,444.38 521.82,443.84 521.82,435.18 v1(523.93,433.07)
  L10-BOT w5: R65.1@535.43,391.73 527.11,400.06 526.18,400.06 522.73,403.51 522.73,413.34 521.28,414.79 521.28,419.72 521.82,420.26 521.82,430.97 v1(523.93,433.07) 521.82,435.18 521.82,447.14 521.25,447.72 521.25,453.9 524.18,456.83 528.09,456.83 C123.2@535.83,464.57
TX_LCL_48MHz: R104.2 U8.1 | length 147.5
  L01-TOP w6: v1(311.02,1385.83) 311.02,1425.89 U8.1@311.67,1426.54
  L10-BOT w6: v1(311.02,1385.83) 342.52,1417.32 R104.2@342.52,1479.33
TX_LED0: R93.1 U7.46 | length 919.8
  L01-TOP w6: v1(678.14,1392.24) U7.46@678.15,1451.76
  L03-SIG w5.5: v1(445.87,1999.01) 445.87,1914.38 409.45,1877.95 409.45,1763.78 476.38,1696.85 476.38,1492.13 508.86,1459.65 636.28,1459.65 678.14,1417.78 v1(678.14,1392.24)
  L10-BOT w6: R93.1@444.02,1949.06 ccw(c432.43,1960.65) 448.82,1960.65 448.82,1996.06 v1(445.87,1999.01)
TX_LPUART_RX: U5.4 U7.14 | length 888.1
  L01-TOP w6: U7.14@697.83,1717.51 v1(697.83,1777.03) ; U5.4@1143.7,1795.26 1177.53,1795.26 1181.48,1799.21 v1(1210.19,1799.21)
  L10-BOT w6: v1(697.83,1777.03) 739.19,1777.03 816.94,1699.27 816.94,1656.3 878.76,1594.49 965.31,1594.49 1051.18,1680.36 1051.18,1776.01 1054.7,1779.53 1098.43,1779.53 1125.98,1807.09 1138.3,1807.09 1146.18,1799.21 v1(1210.19,1799.21)
TX_LPUART_TX: U5.14 U7.4 | length 952.3
  L01-TOP w6: U7.4@742.13,1535.41 800.26,1535.41 810.81,1524.85 810.81,1510.98 v1(823.28,1498.51) ; U5.14@1099.41,1977.35 v1(1099.4,2036.87)
  L03-SIG w5.5: v1(1094.27,1649.86) 1058.8,1649.86 1043.31,1665.35 1043.31,1696.85 1076.52,1730.06 1076.52,1958.41 1099.4,1981.29 v1(1099.4,2036.87)
  L10-BOT w6: v1(823.28,1498.51) 885.51,1498.51 961.8,1574.8 1000,1574.8 1047.11,1621.92 1047.11,1625.98 1057.92,1636.79 1066.38,1636.79 1077.54,1647.95 1092.35,1647.95 v1(1094.27,1649.86)
TX_RF: C12.1 R4.2 U1.4 | length 117.6
  L01-TOP w6: R4.2@274.55,2146.62 277.54,2149.61 C12.1@314.96,2149.61 ccw(c348.32,2182.97) 348.32,2135.79 U1.4@387.26,2135.79
TX_RF_RX: C9.1 L20.1 U7.23 | length 396
  L01-TOP w6: L20.1@279.53,1984.06 ccw(c288.56,1993.08) 288.56,1980.31 C9.1@318.9,1980.32 318.9,1974.35 ccw(c399.54,1974.35) 342.52,1917.32 349.92,1909.93 ccw(c370.08,1930.09) 370.08,1901.57 cw(c370.08,1854.05) 403.68,1887.66 503.94,1787.4 cw(c463.54,1747.01) 520.67,1747.01 U7.23@520.67,1717.51
TX_RF_TX: R1.1 U7.26 | length 87.7
  L01-TOP w6: R1.1@393.7,1691.93 ccw(c438.82,1737.05) 438.82,1673.24 U7.26@476.38,1673.24
TX_RF_TX_HP: R2.1 U7.25 | length 94
  L01-TOP w6: R2.1@393.7,1731.3 cw(c393.7,1700.41) 415.54,1722.25 422.59,1715.21 ccw(c476.38,1769) U7.25@476.38,1692.93
TX_RST_N: R67.2 R101.2 SW4.1 U7.36 | length 1520.9
  L01-TOP w6: SW4.1@185.57,2236.22 223.49,2236.22 v1(224.93,2237.66) ; v1(252.95,1618.11) 254.78,1618.11 263.64,1626.97 R67.2@283.46,1626.97 ; v1(448.82,1453.95) 448.82,1472.82 452.33,1476.34 U7.36@476.38,1476.34
  L06-PWR w6: v1(224.93,2237.66) 151.04,2237.66 46.26,2132.87 46.26,1946.77 70.87,1922.16 70.87,1610.24 112.05,1569.05 232.28,1569.05 ; v1(252.95,1618.11) 232.28,1597.44 232.28,1569.05 ; v1(448.82,1453.95) 409.55,1453.95 404.75,1458.75 368.19,1458.75 334.65,1425.2 248.03,1425.2 232.28,1440.94 232.28,1569.05
  L10-BOT w6: R101.2@185.57,2241.14 189.05,2237.66 v1(224.93,2237.66)
TX_RX_SPARE0: U5.48 U7.48 | length 752.5
  L01-TOP w6: U7.48@717.52,1451.76 717.52,1392.97 735.1,1375.39 789.97,1375.39 805.47,1359.88 v1(823.7,1359.88) ; U5.48@1119.09,1711.61 1119.09,1693.27 v1(1129.96,1682.4)
  L08-SIG w5.5: v1(823.7,1359.88) 837.13,1346.46 891.34,1346.46 979.33,1434.45 979.33,1568.58 1042.38,1631.63 1097.32,1631.63 1129.96,1664.27 v1(1129.96,1682.4)
TX_RX_SPARE2: U5.20 U7.20 | length 1119.6
  L01-TOP w6: v1(578.24,1796.77) 578.98,1796.03 578.98,1718.25 U7.20@579.72,1717.51 ; U5.20@981.3,1977.35 981.3,2036.42 997.05,2052.17 1045.99,2052.17 1052.86,2045.3 1068.32,2045.3 v1(1069.86,2043.76)
  L03-SIG w5.5: v1(578.24,1796.77) 578.24,1824.68 583.38,1829.81 583.38,1836.55 623.81,1876.98 632.89,1876.98 751.97,1996.06 751.97,2035.43 775.59,2059.06 803.15,2059.06 837.37,2093.27 889.7,2093.27 918.02,2121.6 918.02,2172.3 963.24,2217.52 993.95,2217.52 1086.61,2124.86 1086.61,2078.74 1069.86,2061.99 v1(1069.86,2043.76)
TX_RX_SPARE3: U5.44
TX_SWCLK: J8.5 R110.1 U7.2 | length 1510.3
  L01-TOP w6: U7.2@742.13,1496.03 v1(775.59,1496.03)
  L08-SIG w5.5: J8.5@709.84,2573.62 763.78,2519.68 763.78,2292.94 767.02,2289.7 767.02,2192.22 764.48,2189.67 764.48,1993.77 791.7,1966.54 835.52,1966.54 870.56,1931.5 870.56,1736.95 841.61,1708.01 776.81,1708.01 741.87,1673.06 741.87,1529.75 v1(775.59,1496.03)
  L10-BOT w6: J8.5@709.84,2573.62 759.84,2523.62 R110.1@759.84,2394.69
TX_SWDIO: J8.3 R111.1 U7.1 | length 1730.1
  L01-TOP w6: U7.1@742.13,1476.34 807.45,1476.34 819.58,1464.21 R111.1@819.58,1463.22 819.58,1462.24 810.77,1453.43 795.98,1453.43 779,1436.45 779,1422.56 766.15,1409.71 v1@761.94,1409.71
  L08-SIG w5.5: v1(764.05,1407.61) 728.35,1443.31 728.35,1684.84 763.77,1720.26 834.26,1720.26 858.02,1744.02 858.02,1902.98 820.42,1940.58 791.7,1940.58 730.01,2002.27 730.01,2286.54 709.36,2307.19 709.36,2319.8 665.35,2363.8 665.35,2586.61 692.91,2614.17 769.29,2614.17 J8.3@809.84,2573.62
TX_USART1_RX: R62.2 U7.45 | length 737.3
  L01-TOP w6: v1(658.36,1411) 658.45,1411.1 U7.45@658.46,1451.76
  L03-SIG w5.5: v1(200.79,1688.98) 202.68,1688.98 213.22,1699.52 311.81,1699.52 397.3,1614.03 397.3,1466.08 424.49,1438.9 630.46,1438.9 v1(658.36,1411)
  L10-BOT w6: R62.2@173.23,1687.01 175.2,1688.98 v1(200.79,1688.98)
TX_USART1_TX: R63.2 U7.30 | length 561.2
  L01-TOP w6: R63.2@31.5,1600.39 31.5,1617.59 v1(41.07,1627.16) ; v1(413.39,1590.55) 430.87,1590.55 433.39,1593.07 474.97,1593.07 U7.30@476.38,1594.48
  L08-SIG w5.5: v1(41.07,1627.16) 130.44,1716.54 294.8,1716.54 352.57,1658.76 352.57,1651.37 v1(413.39,1590.55)
TX_VFBSD: C2.1 C3.2 C146.1 C158.1 C159.1 J8.1 L1.2 L30.1 U7.40 | length 2494.3
  L01-TOP w10: U7.40@560.04,1451.76 v1(560.04,1385.39) 560.04,1359.46 577.76,1341.73 L30.1@578.55,1341.73
  L01-TOP w12: C3.2@236.22,1704.33 236.22,1705.12 247.64,1716.54 L1.2@277.36,1716.54 277.36,1664.37 v1(278.15,1663.58)
  L05-PWR w15: v1(278.15,1663.58) 278.15,1663.3 293.29,1648.17 293.29,1632.4 302.07,1623.61 324.4,1623.61 407.92,1707.14 430.66,1707.14 488.19,1649.61 488.19,1472.44 500,1460.63 539.37,1460.63 560.06,1439.94 v1@560.06,1385.41
  L06-PWR w15: v1(278.15,1663.58) 278.15,1820.27 206.3,1892.12 206.3,2060.85 385.83,2240.37 385.83,2429.13 481.67,2524.97 861.19,2524.97 J8.1@909.84,2573.62
  L10-BOT w10: C158.1@529.34,1438.67 530.17,1437.84 570.03,1437.84 C159.1@570.87,1437.01 566.8,1432.94 566.8,1393.78 560.04,1387.01 v1(560.04,1385.39)
  L10-BOT w15: C2.1@252.03,1662.33 253.08,1663.38 277.96,1663.38 v1(278.15,1663.58) ; J8.1@909.84,2573.62 926.77,2590.55 C146.1@989.03,2590.55
U3_N: R13.2 U3.9 | length 2610.7
  L01-TOP w5: U3.9@1116.14,2326.77 1128.28,2326.77 1130.62,2324.43 1149.29,2324.43 1149.83,2324.97 1159.48,2324.97 v1(1161.59,2327.08)
  L03-SIG w5: v1@851.26,409 cw(c855.66,404.59) 855.66,410.82 969.57,410.82 ccw(c969.57,522.49) 1048.53,443.53 1094.13,489.13 ccw(c1014.35,568.91) 1127.17,568.91 1127.17,645.95 cw(c1176.88,645.95) 1141.73,681.1 1172.92,712.29 ccw(c1093.26,791.94) 1205.91,791.94 1205.91,1028.6 ccw(c1160.8,1028.6) 1192.7,1060.5 1190.8,1062.39 cw(c1218.12,1089.71) 1179.49,1089.71 1179.49,1094.87 ccw(c1122.64,1094.87) 1162.84,1135.07 1131.49,1166.42 ccw(c1090.64,1125.58) 1090.64,1183.34 1040.9,1183.34 cw(c1040.9,1212.73) 1020.12,1191.95 cw(c1087.7,1259.53) 992.13,1259.53 992.13,1544.51 cw(c1036.74,1544.51) 1005.19,1576.06 1033.32,1604.19 cw(c1066.93,1570.59) 1066.93,1618.11 1089.27,1618.11 ccw(c1089.27,1694.11) 1143.01,1640.37 1144.49,1641.86 ccw(c1100.77,1685.58) 1162.61,1685.47 ccw(c1100.77,1685.58) 1162.61,1685.58 1162.61,1700.65 1162.61,2100.34 cw(c1202.01,2100.34) 1174.19,2128.24 1208.23,2162.29 1209.12,2164.73 1211.94,2168.59 cw(c1223.92,2159.9) 1212.55,2169.37 1212.58,2169.42 ccw(c1198.73,2180.9) 1214.6,2172.42 ccw(c1161.14,2200.79) 1221.66,2200.71 1221.66,2200.85 ccw(c1196.16,2200.85) 1214.19,2218.88 1208.66,2224.41 cw(c1215.3,2231.04) 1205.91,2231.04 1205.91,2299.29 ccw(c1193.1,2299.29) 1202.16,2308.35 1194.4,2316.11 ccw(c1176.73,2298.44) 1176.73,2323.43 1170.79,2323.43 cw(c1170.79,2329.66) v1@1166.39,2325.25
  L10-BOT w5: R13.2@710.63,397.64 718.96,405.96 cw(c721.2,405.96) 719.61,407.55 cw(c725.1,402.07) 725.1,409.82 834.92,409.82 835.46,409.28 844.35,409.28 v1(846.46,407.17)
U3_P: R14.2 U3.8 | length 2567.5
  L01-TOP w5: U3.8@1116.14,2307.09 1128.28,2307.09 1130.62,2309.43 1149.29,2309.43 1149.83,2308.88 1159.48,2308.88 v1(1161.59,2306.78)
  L03-SIG w5: v1@851.26,425.65 ccw(c855.66,430.05) 855.66,423.82 969.52,423.82 ccw(c969.52,522.61) 1039.37,452.76 1084.88,498.27 ccw(c1014.17,568.98) 1114.17,568.98 1114.17,646.08 cw(c1176.57,646.08) 1132.45,690.2 1163.62,721.38 ccw(c1092.91,792.09) 1192.91,792.09 1192.91,1028.52 ccw(c1160.62,1028.52) 1183.45,1051.36 1174.82,1059.99 cw(c1176.83,1061.99) 1174,1061.99 1174,1062.56 ccw(c1172.52,1062.56) 1173.93,1062.98 cw(c1217.95,1089.64) 1166.49,1089.64 1166.49,1094.73 ccw(c1122.29,1094.73) 1153.54,1125.98 1122.36,1157.17 ccw(c1090.55,1125.36) 1090.55,1170.34 1040.8,1170.34 cw(c1040.8,1212.48) 1011,1182.69 1010.86,1182.83 cw(c1087.46,1259.43) 979.13,1259.43 979.13,1544.63 cw(c1036.46,1544.63) 995.92,1585.17 1024.18,1613.43 cw(c1066.87,1570.74) 1066.87,1631.11 1089.2,1631.11 ccw(c1089.2,1694.26) 1133.86,1649.61 1135.22,1650.97 ccw(c1100.5,1685.7) 1149.61,1685.7 1149.61,1706.04 1149.61,2100.34 cw(c1202.01,2100.34) 1149.63,2101.89 cw(c1202.01,2100.34) 1164.96,2137.4 1194.74,2167.18 ; v1@1166.39,2308.6 cw(c1170.79,2304.2) 1170.79,2310.43 1176.67,2310.43 cw(c1176.67,2298.3) 1185.25,2306.88 1192.91,2299.21 1192.91,2231.03 ccw(c1215.25,2231.03) 1199.46,2215.23 1204.96,2209.73 cw(c1196.02,2200.79) 1208.66,2200.79 cw(c1161.14,2200.79) 1203.13,2178.54 cw(c1198.73,2180.9) 1202.58,2177.72 ; 1195.23,2167.75 1201.47,2176.3
  L10-BOT w5: R14.2@710.63,437.01 718.96,428.68 ccw(c721.2,428.68) 719.61,427.09 ccw(c725.1,432.58) 725.1,424.82 834.92,424.82 835.46,425.37 844.35,425.37 v1(846.46,427.47)
U4_N: R64.2 U4.9 | length 1610.1
  L01-TOP w5: U4.9@173.23,1424.21 173.23,1412.08 170.89,1409.73 170.89,1394.08 171.43,1393.53 171.43,1380.87 v1(173.54,1378.77)
  L03-SIG w5: 124.04,1008.52 cw(c150.33,1034.7) 113.23,1034.7 113.23,1164.97 113.23,1165.05 cw(c193.55,1165.05) 124.82,1206.62 125.06,1206.91 143.99,1229.79 ccw(c57.06,1301.71) 169.39,1291.15 169.88,1296.3 ; 124.09,1008.46 129.52,1003.04 cw(c116.72,990.38) 132,999.89 136.17,993.11 cw(c125.05,986.37) 136.73,992.09 ; 136.75,992.05 cw(c92.65,970.5) 141.73,970.5 141.73,504.07 141.73,499.71 142.47,495.6 ccw(c189.26,503.94) 150.28,476.74 152.65,473.33 155.45,470.53 cw(c146.3,461.3) 155.52,470.47 177.18,448.81 ccw(c221.8,493.43) 221.8,430.32 228.84,430.32 233.98,429.27 cw(c223.45,377) 252.86,421.48 257.35,418.51 261.12,414.74 cw(c223.45,377) 261.2,414.67 264.99,410.87 cw(c210.31,356.13) 265.09,410.78 268.83,407.03 271.97,402.88 cw(c210.31,356.13) 286.09,371.77 286.34,370.56 cw(c235.82,358.82) 287.69,358.82 287.69,332.04 ccw(c293.92,332.04) v1@289.51,327.64 ; 169.89,1296.33 169.89,1301.71 169.89,1369.56 cw(c176.12,1369.56) v1@171.71,1373.97
  L10-BOT w5: v1(291.34,322.83) ccw(c291.34,320.18) 288.69,320.18 288.69,283.37 ccw(c348.61,283.37) 306.26,240.98 306.34,240.91 335.32,211.92 ccw(c362.2,238.81) 362.2,200.79 396.01,200.79 ccw(c396.01,214.23) 405.51,204.72 ccw(c384.7,225.54) 414.13,225.54 414.13,240.19 cw(c476.58,240.19) 432.42,284.35 442.21,294.14 cw(c473.48,262.87) 473.48,307.09 475.77,307.09 ccw(c475.77,333.23) 494.25,314.74 498.99,319.48 ccw(c476.65,341.83) 508.25,341.83 ccw(c500.49,341.83) 505.98,347.32 ccw(c504.39,345.73) 504.39,347.97 R64.2@496.06,356.3
U4_P: R65.2 U4.8 | length 1657.2
  L01-TOP w5: v1(153.24,1378.77) 155.34,1380.87 155.34,1389.22 155.89,1389.76 155.89,1409.73 153.54,1412.08 U4.8@153.54,1424.21
  L03-SIG w5: 146.3,461.3 142.64,464.96 139.58,469.37 cw(c189.26,503.94) 129.68,493.25 128.73,498.55 128.73,970.5 ccw(c92.65,970.5) 125.05,986.37 121.45,992.23 120.97,993.02 ccw(c116.72,990.38) 120.25,993.92 118.23,995.94 114.96,999.21 cw(c150.33,1034.7) 114.84,999.33 cw(c150.33,1034.7) 100.23,1034.7 100.23,1165.05 cw(c193.55,1165.05) 127.56,1231.04 127.6,1231.08 ccw(c57.06,1301.71) 156.89,1301.71 156.89,1369.56 ccw(c150.65,1369.56) v1@155.06,1373.97 ; 146.39,461.21 167.99,439.61 ccw(c221.8,493.43) 221.8,417.32 223.45,417.32 cw(c223.45,377) 251.97,405.51 255.83,401.65 cw(c210.31,356.13) 274.69,356.13 274.69,332.04 cw(c268.46,332.04) v1@272.86,327.64
  L10-BOT w5: v1(271.04,322.83) cw(c271.04,320.18) 273.69,320.18 273.69,283.37 ccw(c348.61,283.37) 295.63,230.4 324.75,201.28 ccw(c362.15,238.67) 362.15,185.79 396.08,185.79 ccw(c396.08,214.06) 416.07,194.07 416.14,194.14 ccw(c384.77,225.51) 429.13,225.51 429.13,240.16 cw(c476.66,240.16) 443.04,273.75 452.76,283.46 cw(c473.57,262.65) 473.57,292.09 475.8,292.09 ccw(c475.8,333.15) 504.84,304.11 509.64,308.92 ccw(c476.78,341.77) 523.25,341.77 523.25,341.83 cw(c531,341.83) 525.52,347.32 cw(c527.11,345.73) 527.11,347.97 R65.2@535.43,356.3
USB0_D_N: J2.2 U2.1 U13.1 | length 388.1
  L01-TOP w5: J2.2@190.96,442.9 ccw(c203.73,455.7) 203.73,437.62 251.64,437.62 257.5,436.02 cw(c245.43,391.1) 268.68,431.39 273.93,428.39 278.38,423.93 ccw(c329.25,474.79) 329.25,402.86 394.99,402.86 ccw(c394.99,405.51) v1(397.64,405.51) ccw(c399.74,405.51) 399.74,403.41 414.55,403.41 ccw(c410.99,414.75) 419.4,406.34 449.57,436.51 ccw(c447.31,438.76) 450.5,438.76 cw(c453.69,438.76) 451.43,441.02 465.65,455.24 ccw(c462.63,458.27) 466.91,458.27 466.91,467.66 ccw(c462.91,467.66) 465.74,470.49 cw(c468.57,473.32) 464.57,473.32 U2.1@464.57,485.24
  L10-BOT w5: U13.1@353.74,403.54 ccw(c359.1,408.91) 359.1,401.32 367.46,401.32 ccw(c367.46,403.95) 369.32,402.09 cw(c371.18,400.24) 371.18,402.86 394.99,402.86 ccw(c394.99,405.51) v1(397.64,405.51)
USB0_D_P: J2.3 U2.2 U13.2 | length 411.6
  L01-TOP w5: J2.3@190.94,417.32 cw(c203.73,404.54) 203.73,422.62 245.43,422.62 cw(c245.43,391.1) 267.72,413.39 267.78,413.32 ccw(c329.25,474.79) 329.25,387.86 394.99,387.86 cw(c394.99,385.21) v1(397.64,385.21) cw(c400.29,385.21) 400.29,387.86 414.1,387.86 ccw(c414.1,407.25) 427.8,393.53 463.63,429.36 ccw(c459.12,433.87) 465.5,433.87 476.28,444.66 ccw(c462.7,458.24) 481.91,458.24 481.91,467.66 cw(c485.91,467.66) 483.08,470.49 ccw(c480.25,473.32) 484.25,473.32 U2.2@484.25,485.24
  L10-BOT w5: U13.2@354.33,383.86 cw(c360.28,377.91) 360.28,386.32 373.67,386.32 ccw(c373.67,388.95) 375.53,387.09 cw(c377.39,385.24) 377.39,387.86 394.99,387.86 cw(c394.99,385.21) v1(397.64,385.21)
VBUS_USB: C1.1 C35.1 C36.1 C37.1 C38.2 C46.1 C50.1 C105.1 C120.1 D3.2 D4.2 FB1.1 FB3.1 FB4.1 J2.1 R53.2 R54.2 R79.2 U13.6 U14.7 U14.8 U14.10 U14.11 | length 1058.4
  L01-TOP w10: U14.7@130.24,793.8 130.24,773.57 136.09,767.72 v1(169.29,767.72) ; U14.11@130.24,889.27 130.24,911.46 136.09,917.32 165.35,917.32 173.23,909.45 v1(173.23,901.57) ; U14.8@141.56,821.85 141.63,821.77 163.59,821.77 171.38,813.98 171.38,807.52 v1(171.81,807.09) ; U14.10@141.56,861.22 164.37,861.22 v1(173.23,870.08)
  L01-TOP w15: 279.53,480.31 310.11,480.31 318.9,489.1 D4.2@318.9,521.65 ; D3.2@415.36,826.77 v1(448.82,826.77)
  L10-BOT w6: R79.2@31.5,660.43 31.5,659.45 47.24,643.7 47.24,515.75 78.74,484.25 97.72,484.25 110.68,471.29 v1(236.22,471.29) ; C50.1@157.48,1137.8 C50.1@161.42,1133.86 185.04,1110.24 185.04,1094.49 193.33,1086.19 203.18,1086.19 220.47,1068.9 R53.2@220.47,1067.91
  L10-BOT w12: 314.96,460.63 cw(c293.09,438.76) 324.02,438.76 U13.6@324.02,403.54
  L10-BOT w15: v1(133.86,1114.17) C50.1@157.48,1137.8 ; C50.1@161.42,1137.8 161.42,1168.15 C120.1@166.5,1173.23 ; C120.1@165.35,1173.23 FB4.1@165.35,1229.29 FB3.1@251.97,1229.29
  other v1: 259.84,464.57 283.46,464.57
WIWI_SMA: D5.2 J4.1 U1.6 | length 256.7
  L01-TOP w6: J4.1@385.83,2492.13 385.83,2311.89 385.83,2239.24 ccw(c390.71,2239.24) U1.6@387.26,2235.79
pads on no net: J2.4 J7.6 J8.6 U2.12 U2.13 U2.15 U2.16 U2.17 U2.19 U2.20 U2.23 U2.24 U2.25 U3.2 U3.4 U3.5 U3.6 U3.16 U3.18 U3.19 U4.2 U4.4 U4.5 U4.6 U4.16 U4.18 U4.19 U5.11 U5.12 U5.16 U5.22 U5.28 U5.42 U5.43 U5.46 U7.22 U7.28 U10.1 U11.44 U13.4 U13.5 Y1.1 Y4.4 Y4.9

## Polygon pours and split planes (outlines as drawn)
GND on L01-TOP "NONET_L-01_P-001" (solid, pour order 122): -133.86,2712.6 1374.02,2712.6 1374.02,-94.49 -125.98,-94.49 -125.98,291.34
NetC24_1 on L01-TOP "NONET_L-01_P-001" (solid, pour order 101): 1104.39,347.93 1110.79,354.33 1110.79,413.39 1110.55,413.62 1007.44,413.62 1007.44,393.46 1006.89,392.91 1006.89,348.19 964.43,305.73 964.43,283.11 991,283.11 998,276.11 1095.07,276.11 1104.39,285.43
P3V3 on L01-TOP "NONET_L-01_P-001" (solid, pour order 100): 1155.08,239.92 1155.08,262.79 1163.94,271.65 1174.02,271.65 1187.8,285.43 1187.8,302.36 1181.1,309.06 1125.06,309.06 1125.06,285.43 1096.52,256.89 1096.52,235.25 1099,232.78 1147.94,232.78
P3V3 on L01-TOP "NONET_L-01_P-001" (solid, pour order 91): 236.34,1024.12 236.34,1057.21 175.13,1057.21 175.13,942.98 196.85,921.26 256.89,921.26 261.81,926.18 261.81,946.85 282.48,967.52 323.82,967.52 323.82,1024.12
P1V8 on L01-TOP "NONET_L-01_P-001" (solid, pour order 90): 263.04,695.87 236.34,722.56 175.13,722.56 175.13,631.77 188.78,618.11 326.77,618.11 338.58,629.92 338.58,660.69 323.82,675.45 323.82,695.87
VBUS_USB on L01-TOP "NONET_L-01_P-001" (solid, pour order 88): 151.89,867.44 166.34,881.89 204.72,881.89 231.3,855.31 231.3,813.98 202.49,785.16 202.49,761.3 190.44,749.25 147.72,749.25 133.19,763.78 133.19,771.83 145.5,784.14 153.86,784.14 157.8,788.08 157.8,827.91 185.19,827.91 187.99,830.71 187.99,850.18 181.88,856.3 151.89,856.3
VBUS_USB on L01-TOP "NONET_L-01_P-001" (solid, pour order 87): 212.99,907.87 186.61,907.87 170.7,923.79 136.94,923.79 125.32,912.16 125.32,906.5 144.41,887.4 212.99,887.4
VBUS_USB on L01-TOP "NONET_L-01_P-001" (solid, pour order 82): 210.63,476.38 228.35,494.09 228.35,503.94 246.06,521.65 273.62,521.65 291.34,503.94 291.34,456.69 283.46,448.82 229.33,448.82 217.52,460.63 164.37,460.63 164.37,474.41 164.37,476.38
GND on L02-GND "NONET_L-01_P-001" (solid, pour order 119): -165.35,2724.41 1476.38,2724.41 1476.38,-129.92 -192.91,-129.92 -192.91,452.76
P3V3 on L06-PWR "NONET_L-01_P-001" (solid, remove dead copper, pour order 102): -7.87,1472.44 1259.84,1472.44 1322.83,1409.45 1322.83,66.93 1224.41,-31.5 11.81,-31.5 -35.43,15.75
P1V8 on L06-PWR "NONET_L-01_P-001" (solid, pour order 98): 275.59,1035.43 259.84,1051.18 259.84,1248.03 377.07,1365.26 476.51,1365.26 668.39,1173.38 668.39,1035.43 429.13,1035.43
P1V8 on L06-PWR "NONET_L-01_P-001" (solid, pour order 97): 795.53,1341.72 634.1,1341.72 551.47,1424.35 400.73,1424.35 377.95,1401.57 377.95,1350.39 631.48,1096.87 822.83,1096.87
P1V8 on L06-PWR "NONET_L-01_P-001" (solid, pour order 96): 814.96,1421.26 787.66,1393.95 787.66,1068.26 870.08,985.83 870.08,584.26 951.39,502.95 1113.19,502.95 1145.67,535.43 1145.67,1106.3 1094.49,1157.48 960.63,1157.48 937.01,1181.1 937.01,1358.27 874.02,1421.26
VBUS_USB on L06-PWR "NONET_L-01_P-001" (solid, remove dead copper, pour order 84): 307.09,374.02 480.31,547.24 480.31,883.83 201.2,1162.95 56.65,1162.95 31.5,1137.8 31.5,460.63 118.11,374.02
P3V3 on L10-BOT "NONET_L-01_P-001" (solid, pour order 85): 477.36,1399.12 499.33,1377.15 530,1377.15 530,1403.07 497.05,1436.02 497.05,1448.46 477.36,1448.46
GND on L10-BOT "NONET_L-01_P-001" (solid, pour order 123): -110.24,1897.64 -110.24,2740.16 1397.64,2740.16 1397.64,-137.8 -90.55,-137.8 -90.55,303.15
NetC118_1 on L10-BOT "NONET_L-01_P-001" (solid, pour order 118): 1160.7,2350.39 1149.5,2339.19 1149.5,2287.29 1102.36,2240.16 909.45,2240.16 901.57,2248.03 901.57,2271.65 905.51,2275.59 1102.73,2275.59 1124.83,2297.68 1124.83,2346.46
NetC125_1 on L10-BOT "NONET_L-01_P-001" (solid, pour order 117): 203.74,1423.23 234.25,1423.23 238.19,1419.29 293.31,1419.29 307.09,1433.07 307.09,1456.69 304.13,1459.65 220.47,1459.65 203.74,1442.91
NetC121_1 on L10-BOT "NONET_L-01_P-001" (solid, pour order 116): 217.36,1521.11 217.36,1467.73 225.45,1459.65 276.57,1459.65 286.42,1469.49 304.13,1469.49 304.13,1489.17 293.31,1500 258.76,1500 237.65,1521.11
NetC126_1 on L10-BOT "NONET_L-01_P-001" (solid, pour order 115): 85.63,1606.22 97.07,1617.65 97.07,1628.56 102.36,1633.86 120.82,1633.86 133.86,1620.82 133.86,1614.17 140.13,1614.17 148.86,1605.44 148.86,1582.57 110.6,1582.57 108.51,1580.47 85.63,1580.47
NetC51_1 on L10-BOT (solid, pour order 114): 1042.4,2346.19 1061.53,2346.19 1062.69,2345.03 1080.71,2363.05 1080.71,2422.98 1065.95,2437.74 1051.18,2437.74 1051.18,2424.06 1039.37,2412.25 1024.1,2412.25 1014.76,2402.92 1014.76,2385.29 1020.14,2379.91 1042.78,2379.91 1042.4,2379.52
NetC117_1 on L10-BOT "NONET_L-01_P-001" (solid, pour order 113): 1057.09,2462.6 1057.09,2442.91 1061.02,2442.91 1085.63,2418.31 1085.63,2387.53 1142.45,2387.53 1150.59,2395.67 1150.59,2415.35 1132.87,2433.07 1110.24,2433.07 1080.71,2462.6 1072.87,2462.6
NetC118_1 on L10-BOT "NONET_L-01_P-001" (solid, pour order 110): 1149.5,2337.6 1171.9,2360 1187.99,2360 1187.99,2380.16 1182.33,2385.83 1125.51,2385.83 1100.15,2360.48 1100.15,2337.6
NetC61_2 on L10-BOT "NONET_L-01_P-001" (solid, pour order 109): 751.97,588.58 792.13,588.58 814.96,565.75 814.96,545.98 797.52,528.54 754.92,528.54 754.92,565.94 751.97,568.9
DPLL_FILTER on L10-BOT "NONET_L-01_P-001" (solid, pour order 105): 660.43,588.82 670.04,598.43 734.25,598.43 744.09,588.58 744.09,553.15 741.14,550.2 741.14,530.54 754.18,517.51 754.18,494.63 720.1,494.63 683.31,531.42 683.31,545.78 660.43,568.66
NetC47_1 on L10-BOT "NONET_L-01_P-001" (solid, pour order 104): 399.77,580.95 390.79,571.97 390.79,569.29 374.65,569.29 366.14,560.78 366.14,535.43 375.44,526.13 420.44,526.13 420.44,578.74 422.65,580.95
P1V8 on L10-BOT "NONET_L-01_P-001" (solid, pour order 103): 363.68,651.08 338.58,625.98 267.72,625.98 249.69,644.01 249.69,685.53 267.41,703.25 308.56,703.25 310.53,701.28 361.53,701.28 363.68,699.13
P3V3 on L10-BOT "NONET_L-01_P-001" (solid, pour order 94): 148.74,926.06 144.69,930.12 123.03,930.12 123.03,957.4 132.05,966.41 293.43,966.41 303.15,956.69 341.04,956.69 351.87,945.87 351.87,928.15 301.8,928.15 299.7,926.06
VBUS_USB on L10-BOT "NONET_L-01_P-001" (solid, pour order 93): 237.2,512.8 272.64,512.8 290.19,530.35 290.19,542.4 343.43,542.4 354.33,531.5 354.33,468.5 330.71,444.88 233.27,444.88 223.43,454.72 223.43,482.77 236.22,495.56
VBUS_USB on L10-BOT "NONET_L-01_P-001" (solid, pour order 89): 182.58,810.05 173.23,819.4 160.56,819.4 157.8,816.63 157.8,751.65 165.35,744.09 208.68,744.09 219,754.41 219,810.05
VBUS_USB on L10-BOT "NONET_L-01_P-001" (solid, pour order 86): 210.63,907.48 200.79,917.32 171.26,917.32 161.42,907.48 161.42,866.14 169.29,858.27 206.69,858.27 210.63,862.2 210.63,891.88
DPLL_FILTER on L05-PWR "NONET_L-01_P-001" (solid, pour order 106): 559.96,825.61 559.96,778.89 608.63,730.22 608.63,551.42 631.51,528.54 756.14,528.54 783.46,555.86 783.46,753.27 715.06,821.67
P1V8 on L05-PWR (solid, pour order 107): 243.31,400.08 320.56,322.83 847.88,322.83 928.15,403.11 928.15,460.63 1090.55,460.63 1122.05,492.13 1122.05,669.29 236.22,669.29 215.47,648.54 215.47,460.63 243.31,460.63
P3V3 on L05-PWR "NONET_L-01_P-001" (solid, pour order 108): 35.43,968.5 35.43,2598.43 70.87,2633.86 1181.1,2633.86 1236.22,2578.74 1236.22,43.31 1216.54,23.62 59.06,23.62 27.56,55.12
GND on L04-GND "NONET_L-01_P-001" (solid, pour order 83): -165.35,2724.41 1476.38,2724.41 1476.38,-129.92 -192.91,-129.92 -192.91,452.76
GND on L07-GND "NONET_L-01_P-001" (solid, pour order 120): -165.35,2724.41 1476.38,2724.41 1476.38,-129.92 -192.91,-129.92 -192.91,452.76
GND on L09-GND "NONET_L-01_P-001" (solid, pour order 121): -165.35,2724.41 1476.38,2724.41 1476.38,-129.92 -192.91,-129.92 -192.91,452.76

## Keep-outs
Keep-Out Layer:
  lines w0.5: 2379.06,-1421.42 ccw(c2379.02,-1381.3) 2419.13,-1381.3

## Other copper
L01-TOP:
  pour cut-out: 125.32,906.5 144.41,906.5 144.41,887.4 125.32,887.4 125.32,889.27
  pour cut-out: 125.98,771.65 157.8,771.65 157.8,788.56 125.32,788.56
  pour cut-out: 433.07,606.3 433.07,681.1 614.17,681.1 614.17,498.03 432.5,498.03 432.5,602.36
  pour cut-out: 956.69,2387.41 1116.14,2387.41 1116.14,2227.36 956.69,2227.36 956.69,2302.17
  pour cut-out: 73.82,1583.66 233.27,1583.66 233.27,1424.21 73.82,1424.21

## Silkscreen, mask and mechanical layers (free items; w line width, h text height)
Top Overlay:
  lines w10: 283.46,75.29 919.53,75.29 919.53,385.83 283.46,385.83 283.46,75.29
  text "RCB Header in future" at 366.17,87.26 h60
Board Layer Stack Bottom Overlay:
  drawing of 9 lines, arcs and shapes, not listed
  text "RCB STM32WL3 V1 / Julian St. James / Ahmad Byagowi / Nobuyasu Shiga" at 936.22,2104.72 h59.06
